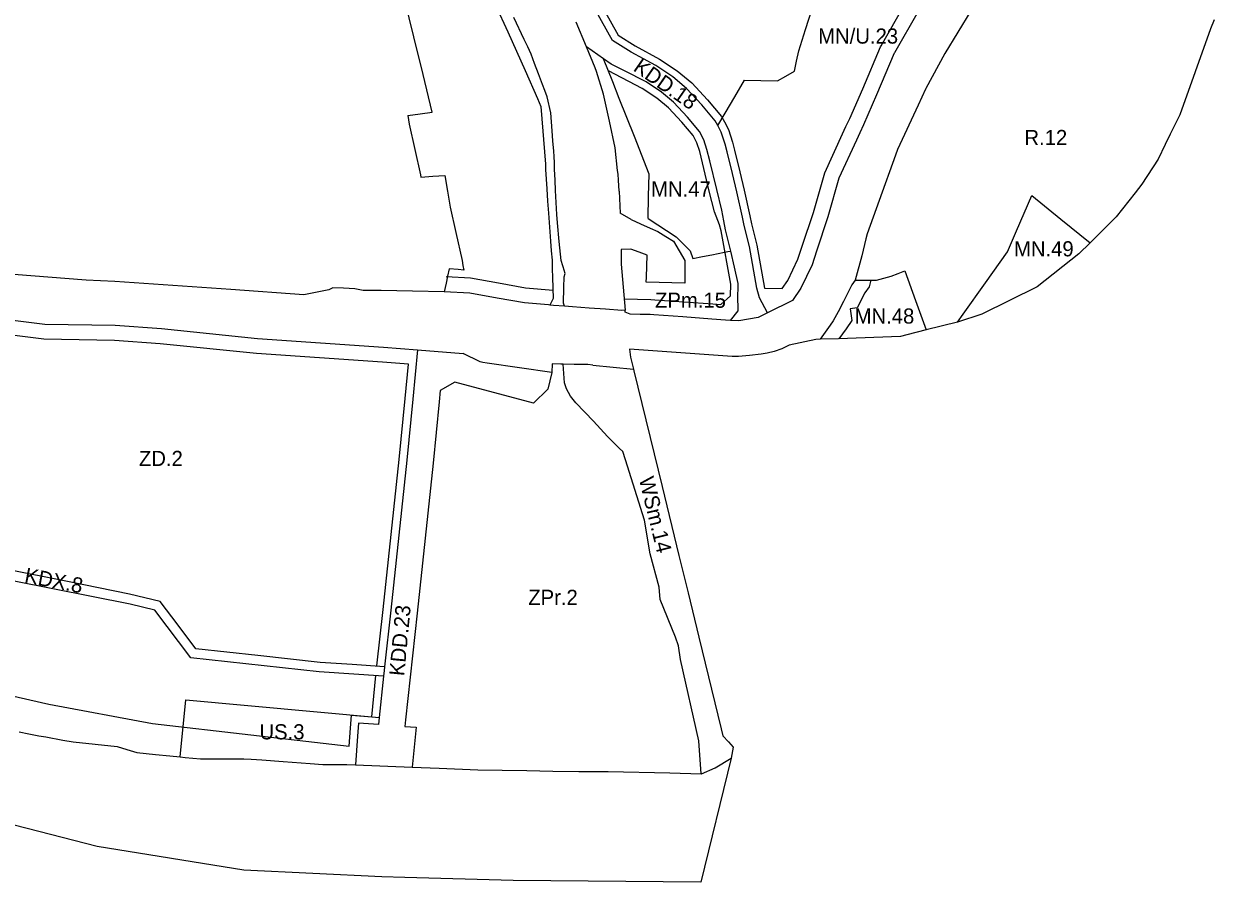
# Model space of a CAD drawing. Extents: x 7431080 to 7433370, y 5546450 to 5548428.
# Drawn here: x 7432562 to 7433191, y 5546450 to 5546903 of the extents above; entities that cross this region are included whole.
import ezdxf

# ---------------------------------------------------------------- set-up
doc = ezdxf.new("R2010")
doc.units = 0
for name, color, linetype in [('Linie Rozgraniczajace', 7, 'Continuous'), ('nieprzekraczalna linia zabudowy', 7, 'Continuous'), ('oznaczenia_przeznaczen', 7, 'Continuous')]:
    doc.layers.add(name, color=color, linetype=linetype)

msp = doc.modelspace()

# ---------------------------------------------------------------- linework, layer by layer
at = {"layer": 'Linie Rozgraniczajace'}
for p, q in [((7432873.26, 5546872.67), (7432868.47, 5546884.8)), ((7432876.7, 5546814.99), (7432877.27, 5546803.37)), ((7432882.97, 5546799.95), (7432877.27, 5546803.37)), ((7432752.74, 5546563.93), (7432752.53, 5546561.94)), ((7432763.56, 5546532.4), (7432769.55, 5546531.97)), ((7432769.55, 5546531.97), (7432767.38, 5546510.97)), ((7432559.77, 5546529.51), (7432564.97, 5546528.5)), ((7432564.97, 5546528.5), (7432570.17, 5546527.5)), ((7432570.17, 5546527.5), (7432573.86, 5546526.84)), ((7432573.86, 5546526.84), (7432582.97, 5546525.21)), ((7432582.97, 5546525.21), (7432588.39, 5546524.24)), ((7432588.39, 5546524.24), (7432599.96, 5546523.07)), ((7432599.96, 5546523.07), (7432611.52, 5546521.9)), ((7432611.52, 5546521.9), (7432616.71, 5546520.26)), ((7432616.71, 5546520.26), (7432621.91, 5546518.62)), ((7432621.91, 5546518.62), (7432631.9, 5546517.62)), ((7432631.9, 5546517.62), (7432639.36, 5546516.86)), ((7432639.36, 5546516.86), (7432644.85, 5546516.31)), ((7432644.85, 5546516.31), (7432647.48, 5546516.04)), ((7432647.48, 5546516.04), (7432655.6, 5546515.22)), ((7432655.6, 5546515.22), (7432661.77, 5546515.25)), ((7432661.77, 5546515.25), (7432669.27, 5546515.3)), ((7432669.27, 5546515.3), (7432678.55, 5546515.35)), ((7432678.55, 5546515.35), (7432682.3, 5546515.21)), ((7432682.3, 5546515.21), (7432688, 5546514.77)), ((7432688, 5546514.77), (7432699.21, 5546513.89)), ((7432699.21, 5546513.89), (7432713.43, 5546512.79)), ((7432713.43, 5546512.79), (7432720.17, 5546512.26)), ((7432720.17, 5546512.26), (7432724.66, 5546512.25)), ((7432724.66, 5546512.25), (7432732.9, 5546512.24)), ((7432732.9, 5546512.24), (7432737.37, 5546512.22)), ((7432737.37, 5546512.22), (7432767.38, 5546510.97)), ((7432927.32, 5546510.6), (7432935.83, 5546515.71)), ((7432767.38, 5546510.97), (7432781.58, 5546510.34)), ((7432781.58, 5546510.34), (7432802.1, 5546509.49)), ((7432802.1, 5546509.49), (7432814.96, 5546509.29)), ((7432814.96, 5546509.29), (7432827.83, 5546509.09)), ((7432827.83, 5546509.09), (7432841.56, 5546508.88)), ((7432841.56, 5546508.88), (7432855.29, 5546508.68)), ((7432855.29, 5546508.68), (7432870.94, 5546508.54)), ((7432870.94, 5546508.54), (7432903.39, 5546507.86)), ((7432903.39, 5546507.86), (7432919.91, 5546507.33)), ((7432919.91, 5546507.33), (7432920.19, 5546507.32)), ((7432920.19, 5546507.32), (7432927.32, 5546510.6))]:
    msp.add_line(p, q, dxfattribs=at)
for points in [[(7432765.1, 5546854.86), (7432771.53, 5546855.75), (7432777.96, 5546856.64), (7432773.13, 5546876.48), (7432768.29, 5546896.32), (7432758.63, 5546936), (7432749.94, 5546963.17), (7432741.24, 5546990.34), (7432737.04, 5547002.99), (7432732.83, 5547015.64), (7432729.94, 5547026.01), (7432727.04, 5547036.39), (7432716.21, 5547073.96), (7432705.39, 5547111.54), (7432703.85, 5547118.25)], [(7432928.81, 5546849.61), (7432932.61, 5546856.03), (7432937.75, 5546864.74), (7432942.9, 5546873.44), (7432951.57, 5546873.3), (7432960.23, 5546873.17), (7432964.71, 5546875.68), (7432969.18, 5546878.19), (7432970.36, 5546883.59), (7432971.53, 5546889), (7432975.11, 5546900.33), (7432978.69, 5546911.66), (7432996.45, 5546991.58), (7432998.07, 5546998.45), (7432999.69, 5547005.32)], [(7432955.06, 5546750.76), (7432950.71, 5546758.7), (7432949.36, 5546763.67), (7432945.46, 5546785.65), (7432942.68, 5546796.77), (7432941.82, 5546801.18), (7432938.78, 5546814.56), (7432936.46, 5546824.21), (7432933.7, 5546835.67), (7432932.65, 5546839.74), (7432930.62, 5546846), (7432928.81, 5546849.61), (7432927.36, 5546852.11), (7432920.32, 5546860.57), (7432912.3, 5546869.19), (7432904.95, 5546875.29), (7432895.97, 5546881.22), (7432883.06, 5546888.22), (7432873.16, 5546894.5), (7432858.21, 5546921.36)], [(7432811.29, 5546913.14), (7432817.81, 5546899.04), (7432827.09, 5546878.6), (7432833.5, 5546863.85), (7432835.33, 5546859.64)], [(7433034.52, 5546909.71), (7433022.02, 5546887.92), (7433021.94, 5546887.76), (7433012.63, 5546865.7), (7433005.72, 5546850), (7433003.71, 5546845.65), (7433001.94, 5546841.82), (7432992.74, 5546821.77), (7432986.88, 5546801.38), (7432980.91, 5546783.33), (7432978.51, 5546776.04), (7432972.65, 5546763.77), (7432968.22, 5546757.31), (7432955.06, 5546750.76), (7432950.05, 5546748.27), (7432939.92, 5546746.42), (7432935.47, 5546746.73)], [(7433062.31, 5546910.14), (7433048.7, 5546887.58), (7433038.57, 5546869.04), (7433038.47, 5546868.82), (7433034.51, 5546860.25), (7433023.73, 5546836.96), (7433023.7, 5546836.85), (7433022.61, 5546833.85), (7433013.97, 5546810.09), (7433007.55, 5546792.39)], [(7432847.76, 5546754.18), (7432847.24, 5546755.8), (7432847.41, 5546764.14), (7432847.56, 5546769.78), (7432848.09, 5546771.46), (7432847.04, 5546774.93), (7432846.85, 5546775.56), (7432845.98, 5546778.4), (7432845.04, 5546788.28), (7432844.1, 5546798.15), (7432843.71, 5546802.67), (7432843.41, 5546808.87), (7432843.09, 5546815.25), (7432842.84, 5546820.8), (7432842.58, 5546826.55), (7432842.57, 5546829.93), (7432842.31, 5546833.16), (7432842.09, 5546836.02), (7432841.71, 5546841.42), (7432841.32, 5546846.82), (7432840.98, 5546851.53), (7432840.63, 5546856.24), (7432838.67, 5546864.68), (7432837.43, 5546868), (7432836.19, 5546871.32), (7432834.11, 5546876.79), (7432832.02, 5546882.26), (7432831.12, 5546884.74), (7432830.21, 5546887.21), (7432828.37, 5546891.09), (7432826.52, 5546894.97), (7432820.99, 5546906.58)], [(7432935.47, 5546746.73), (7432939.59, 5546751.73), (7432939.43, 5546754.45), (7432939.36, 5546757.34), (7432939.57, 5546766.18), (7432937.65, 5546774.76), (7432935.73, 5546783.34), (7432934.32, 5546788.97), (7432932.91, 5546794.6), (7432932.01, 5546799.25), (7432930.89, 5546804.87), (7432928.17, 5546815.8), (7432924.61, 5546830.88), (7432923.04, 5546836.94), (7432921.38, 5546842.08), (7432919.02, 5546846.51), (7432912.81, 5546853.96), (7432905.42, 5546861.91), (7432898.98, 5546867.25), (7432890.89, 5546872.59), (7432879.53, 5546878.53), (7432872.37, 5546882.05), (7432868.47, 5546884.8), (7432859.46, 5546891.16), (7432854.03, 5546904.13)], [(7433190.89, 5546905.3), (7433189, 5546900.53), (7433172.72, 5546855.21), (7433167.58, 5546844.94), (7433165.02, 5546839.63), (7433161.28, 5546831.87), (7433152.71, 5546818.62), (7433149.1, 5546814.02), (7433139.14, 5546801.38), (7433137.74, 5546799.89), (7433125.39, 5546787.67), (7433119.48, 5546781.82), (7433097.34, 5546764.48), (7433068.12, 5546749.98), (7433055.4, 5546745.76), (7433038.8, 5546741.66), (7433028.52, 5546739.13), (7433025.26, 5546738.2), (7432992.54, 5546737.06), (7432982.75, 5546736.88), (7432980.48, 5546736.64), (7432966.43, 5546733.72), (7432962.61, 5546731.79), (7432958.53, 5546730.27), (7432954.83, 5546729.43), (7432951.71, 5546728.98), (7432945.55, 5546728.12), (7432939.61, 5546727.72), (7432936.4, 5546727.73), (7432882.09, 5546731.49), (7432882.64, 5546727.32), (7432884.19, 5546720.98), (7432884.43, 5546720.02), (7432899.32, 5546659.02), (7432908.23, 5546622.58)], [(7432876.7, 5546814.99), (7432876.4, 5546820.78), (7432876.07, 5546823.91), (7432875.87, 5546825.9), (7432874.65, 5546837.74), (7432871.49, 5546851.95), (7432868.33, 5546866.15), (7432864.76, 5546878.15), (7432863.94, 5546880.1), (7432859.46, 5546891.16)], [(7432876.73, 5546863.89), (7432873.26, 5546872.67)], [(7432892.01, 5546800.55), (7432892.25, 5546812.24), (7432892.5, 5546823.82), (7432884.7, 5546843.85), (7432876.73, 5546863.89)], [(7432835.33, 5546859.64), (7432837.79, 5546829.27), (7432837.83, 5546826.43), (7432838.15, 5546821.26), (7432838.46, 5546816.1), (7432838.88, 5546809.7), (7432839.3, 5546803.3), (7432839.87, 5546795.9), (7432840.43, 5546788.49), (7432840.84, 5546783.5), (7432841.25, 5546778.52), (7432841.37, 5546773.91), (7432841.49, 5546769.3), (7432841.82, 5546758.34), (7432840.56, 5546755.78), (7432840.09, 5546754.82)], [(7432765.1, 5546854.86), (7432765.81, 5546850.24), (7432768.77, 5546836.91), (7432771.73, 5546823.57), (7432771.99, 5546822.29)], [(7432771.99, 5546822.29), (7432778.33, 5546822.77), (7432784.66, 5546823.25), (7432786, 5546814.89), (7432787.35, 5546806.53), (7432790.36, 5546793.15)], [(7433055.4, 5546745.76), (7433058.41, 5546750.02), (7433070.05, 5546766.48), (7433081.69, 5546782.93), (7433086.44, 5546793.94), (7433090.48, 5546803.29), (7433094.52, 5546812.63), (7433109.95, 5546800.15), (7433125.39, 5546787.67)], [(7432892.01, 5546800.55), (7432906.8, 5546790.85), (7432910.46, 5546787.16), (7432914.12, 5546783.46), (7432915.61, 5546779.47), (7432920.64, 5546780.44), (7432925.67, 5546781.41), (7432928.96, 5546782.04), (7432932.26, 5546782.67)], [(7432882.97, 5546799.95), (7432887.98, 5546797.7), (7432892.98, 5546795.45), (7432897.13, 5546793.65), (7432901.25, 5546791.08), (7432905.36, 5546788.5), (7432908.32, 5546783.42), (7432911.28, 5546778.34), (7432911.35, 5546771.11), (7432911.4, 5546766.35), (7432890.94, 5546766.9), (7432891.18, 5546769.5), (7432891.29, 5546775.34), (7432891.39, 5546781.18), (7432887.15, 5546782.77), (7432882.9, 5546784.36), (7432877.74, 5546784.2)], [(7432790.36, 5546793.15), (7432793.7, 5546778.27), (7432794.16, 5546775.75), (7432794.61, 5546773.24), (7432791.62, 5546773.56), (7432786.85, 5546773.86), (7432786.11, 5546770.08), (7432785.37, 5546766.3)], [(7433007.55, 5546792.39), (7433006.94, 5546789.84), (7433004.79, 5546780.78), (7433001.38, 5546767.92), (7432999.51, 5546765.44), (7432995.09, 5546756.72), (7432992.24, 5546751.3)], [(7432877.74, 5546784.2), (7432877.76, 5546776.37), (7432879.79, 5546752.08)], [(7432932.26, 5546782.67), (7432933.99, 5546783.01), (7432935.73, 5546783.34)], [(7432741.42, 5546762.54), (7432737.01, 5546763.45), (7432731.19, 5546763.69), (7432725.46, 5546763.93), (7432723.41, 5546762.88), (7432710.2, 5546760.25), (7432671.56, 5546763.11), (7432640.92, 5546765.2), (7432610.28, 5546767.29), (7432595.27, 5546768.02), (7432557.05, 5546770.94)], [(7433001.38, 5546767.92), (7433005.18, 5546767.93), (7433012.65, 5546767.96), (7433016.52, 5546768.99), (7433020.38, 5546770.01), (7433023.94, 5546771.44), (7433027.49, 5546772.86), (7433033.16, 5546757.26), (7433038.8, 5546741.66)], [(7432785.37, 5546766.3), (7432784.81, 5546764.09), (7432784.25, 5546761.88)], [(7432935.47, 5546746.73), (7432932.77, 5546746.92), (7432925.61, 5546747.43), (7432910.29, 5546748.54), (7432894.97, 5546749.64), (7432893, 5546749.78), (7432887.74, 5546749.87), (7432882.47, 5546749.96), (7432879.84, 5546751.02), (7432879.79, 5546752.08), (7432878.14, 5546751.97), (7432869.45, 5546752.59), (7432860.77, 5546753.21), (7432852.05, 5546753.83), (7432847.76, 5546754.18), (7432842.01, 5546754.66), (7432840.09, 5546754.82), (7432839.36, 5546754.88), (7432826.67, 5546755.92), (7432812.21, 5546758.53), (7432797.75, 5546761.13), (7432784.25, 5546761.88), (7432767.61, 5546762.17), (7432750.96, 5546762.47), (7432741.42, 5546762.54)], [(7432992.24, 5546751.3), (7432989.75, 5546746.56), (7432988.07, 5546744.24), (7432982.75, 5546736.88)], [(7432535.17, 5546749.53), (7432573.37, 5546744.73), (7432610.6, 5546744.14)], [(7432610.6, 5546744.14), (7432634.97, 5546742.39), (7432685.76, 5546737.18), (7432752.31, 5546732.6), (7432770.22, 5546731.21)], [(7432770.22, 5546731.21), (7432767.65, 5546705.14), (7432764.5, 5546672.94), (7432756.02, 5546593.69), (7432752.74, 5546563.93)], [(7432770.22, 5546731.21), (7432794.33, 5546729.33)], [(7432862.8, 5546723.1), (7432860.07, 5546723.36), (7432852.94, 5546723.49), (7432847.02, 5546723.6), (7432845.81, 5546723.62), (7432841.38, 5546723.78), (7432841.18, 5546719.25), (7432824.08, 5546721.71), (7432806.98, 5546724.17), (7432804.74, 5546724.49), (7432803.23, 5546724.8), (7432794.33, 5546729.33)], [(7432841.18, 5546719.25), (7432838.95, 5546710.44), (7432831.48, 5546703.04), (7432789.97, 5546714.17), (7432782.16, 5546709.64)], [(7432847.81, 5546713.81), (7432847.02, 5546723.6)], [(7432862.8, 5546723.1), (7432884.19, 5546720.98)], [(7432919.91, 5546507.33), (7432918.82, 5546524.83), (7432909, 5546567.72), (7432907.99, 5546575.03), (7432906.48, 5546579.47), (7432898.25, 5546599.39), (7432897.85, 5546605.99), (7432893.11, 5546623.47), (7432890.14, 5546641.22), (7432879.97, 5546673.12), (7432878.6, 5546677.47), (7432876.78, 5546679.15), (7432870.57, 5546685.51), (7432863.09, 5546693.56), (7432853.83, 5546703.24), (7432850.9, 5546706.7), (7432848.89, 5546710.58), (7432847.81, 5546713.81)], [(7432782.16, 5546709.64), (7432781.58, 5546703.77), (7432778.4, 5546671.28), (7432769.94, 5546592.18), (7432763.92, 5546535.95), (7432763.56, 5546532.4)], [(7432653.11, 5546573.41), (7432643.73, 5546585.86), (7432634.34, 5546598.3), (7432626.24, 5546600.26), (7432618.13, 5546602.23), (7432585.37, 5546608.83), (7432552.61, 5546615.42), (7432519.74, 5546622.4), (7432486.87, 5546629.37), (7432462.82, 5546633.85), (7432438.77, 5546638.33)], [(7432650.42, 5546568.68), (7432631.42, 5546593.86), (7432618.5, 5546597), (7432516.99, 5546617.06), (7432441.27, 5546633.46), (7432427.92, 5546595.44)], [(7432908.23, 5546622.58), (7432913.04, 5546602.91), (7432918.78, 5546579.45), (7432930.59, 5546531.09), (7432931.49, 5546527.39), (7432934.35, 5546524.24), (7432936.9, 5546521.42), (7432935.83, 5546515.71), (7432919.88, 5546450.2), (7432820.67, 5546451.02), (7432763.46, 5546452.71), (7432751.33, 5546453.06), (7432678.54, 5546456.61), (7432601.02, 5546469.08), (7432526.29, 5546488.21)], [(7432752.23, 5546558.95), (7432718.27, 5546561.17), (7432650.42, 5546568.68)], [(7432752.74, 5546563.93), (7432735.73, 5546565.04), (7432718.71, 5546566.15), (7432685.91, 5546569.78), (7432653.11, 5546573.41)], [(7432752.53, 5546561.94), (7432752.23, 5546558.95), (7432749.97, 5546537.09)], [(7432644.85, 5546516.31), (7432647.81, 5546546.51), (7432749.97, 5546537.09)], [(7432749.97, 5546537.09), (7432749.59, 5546533.42), (7432739.01, 5546534.19), (7432738.49, 5546527.21), (7432737.37, 5546512.22)]]:
    msp.add_lwpolyline(points, dxfattribs=at)
at = {"layer": 'nieprzekraczalna linia zabudowy'}
for p, q in [((7433014.97, 5546891.7), (7433027.55, 5546913.64)), ((7433005.28, 5546868.87), (7433014.67, 5546891.11)), ((7433014.67, 5546891.11), (7433014.97, 5546891.7)), ((7432998.43, 5546853.29), (7433005.28, 5546868.87)), ((7432996.45, 5546849.01), (7432998.43, 5546853.29)), ((7432940.35, 5546825.15), (7432942.68, 5546815.47)), ((7432942.68, 5546815.47), (7432945.74, 5546802)), ((7432945.74, 5546802), (7432946.58, 5546797.63)), ((7432946.58, 5546797.63), (7432949.38, 5546786.48)), ((7432949.38, 5546786.48), (7432953.41, 5546763.72)), ((7432735.32, 5546538.44), (7432745.99, 5546537.46))]:
    msp.add_line(p, q, dxfattribs=at)
for points in [[(7432855.1, 5546956.06), (7432854.83, 5546948.8), (7432856.4, 5546937.18), (7432858.25, 5546932.88), (7432861.86, 5546923.03), (7432876.16, 5546897.34), (7432885.09, 5546891.67), (7432898.03, 5546884.65), (7432907.34, 5546878.51), (7432915.05, 5546872.1), (7432923.32, 5546863.22), (7432930.66, 5546854.41), (7432932.33, 5546851.51), (7432934.33, 5546847.52), (7432936.49, 5546840.85), (7432937.58, 5546836.64), (7432940.35, 5546825.15)], [(7432930.31, 5546755.12), (7432935.42, 5546759.77), (7432935.56, 5546765.78), (7432930.58, 5546794.01), (7432929.58, 5546797.23), (7432926.99, 5546804), (7432924.28, 5546814.86), (7432920.73, 5546829.92), (7432919.2, 5546835.82), (7432917.68, 5546840.51), (7432915.68, 5546844.27), (7432909.81, 5546851.32), (7432902.67, 5546859), (7432896.59, 5546864.03), (7432888.86, 5546869.14), (7432870.96, 5546878.5)], [(7432953.41, 5546763.72), (7432962.8, 5546763.55), (7432965.7, 5546767.78), (7432971.07, 5546779.03), (7432973.31, 5546785.84), (7432979.23, 5546803.74), (7432985.22, 5546824.56), (7432994.67, 5546845.17), (7432996.45, 5546849.01)], [(7432785.28, 5546769.83), (7432798.22, 5546769.11), (7432812.92, 5546766.47), (7432827.19, 5546763.89), (7432841.81, 5546762.69)], [(7433009.66, 5546767.95), (7433008.71, 5546764.35), (7433006.32, 5546761.19), (7433002.38, 5546753.41)], [(7432879.29, 5546758.02), (7432893.35, 5546757.78), (7432895.54, 5546757.62), (7432910.87, 5546756.52), (7432926.18, 5546755.41), (7432930.31, 5546755.12)], [(7433002.39, 5546753.41), (7432998.63, 5546752.85), (7432999.55, 5546746.67), (7432996.57, 5546742.33), (7432994.55, 5546739.55), (7432992.76, 5546737.07)], [(7432765.45, 5546723.56), (7432751.73, 5546724.62), (7432685.08, 5546729.21), (7432634.28, 5546734.42), (7432610.25, 5546736.14), (7432572.81, 5546736.74), (7432534.47, 5546741.56)], [(7432748.76, 5546564.37), (7432752.04, 5546594.12), (7432760.52, 5546673.35), (7432763.67, 5546705.53), (7432765.45, 5546723.56)], [(7432426.16, 5546590.03), (7432553.23, 5546549.34), (7432575.57, 5546544.1), (7432630.17, 5546533.94), (7432734.09, 5546522)], [(7432745.99, 5546537.46), (7432748.17, 5546559.22)], [(7432734.09, 5546522), (7432734.8, 5546531.49), (7432735.32, 5546538.44)]]:
    msp.add_lwpolyline(points, dxfattribs=at)

# ---------------------------------------------------------------- texts
at = {"layer": 'oznaczenia_przeznaczen'}
for s, p in [('MN/U.23', (7432981.77, 5546892.8)), ('R.12', (7433090.68, 5546839.25)), ('R.12', (7433090.68, 5546839.25)), ('MN.47', (7432893.55, 5546812.1)), ('MN.49', (7433085.17, 5546780.52)), ('ZPm.15', (7432895.61, 5546753.37)), ('ZPm.15', (7432895.61, 5546753.37)), ('ZPm.15', (7432895.61, 5546753.37)), ('MN.48', (7433001.02, 5546745.02)), ('ZD.2', (7432623.07, 5546669.87)), ('ZD.2', (7432623.07, 5546669.87)), ('ZPr.2', (7432828.66, 5546596.55)), ('ZPr.2', (7432828.66, 5546596.55)), ('ZPr.2', (7432828.66, 5546596.55)), ('US.3', (7432686.73, 5546525.57)), ('US.3', (7432686.73, 5546525.57)), ('US.3', (7432686.73, 5546525.57))]:
    msp.add_text(s, height=8, dxfattribs=at).set_placement(p)
for s, rotation, p in [('KDD.18', 325.21133, (7432883.61, 5546878.86)), ('WSm.14', 283.77082, (7432887.03, 5546663.11)), ('WSm.14', 283.77082, (7432887.03, 5546663.11)), ('WSm.14', 283.77082, (7432887.03, 5546663.11)), ('KDX.8', 349.14339, (7432562.26, 5546608.45)), ('KDX.8', 349.14339, (7432562.26, 5546608.45)), ('KDX.8', 349.14339, (7432562.26, 5546608.45)), ('KDD.23', 84.67218, (7432763.17, 5546558.78))]:
    msp.add_text(s, height=8, rotation=rotation, dxfattribs=at).set_placement(p)

doc.saveas('drawing.dxf')
